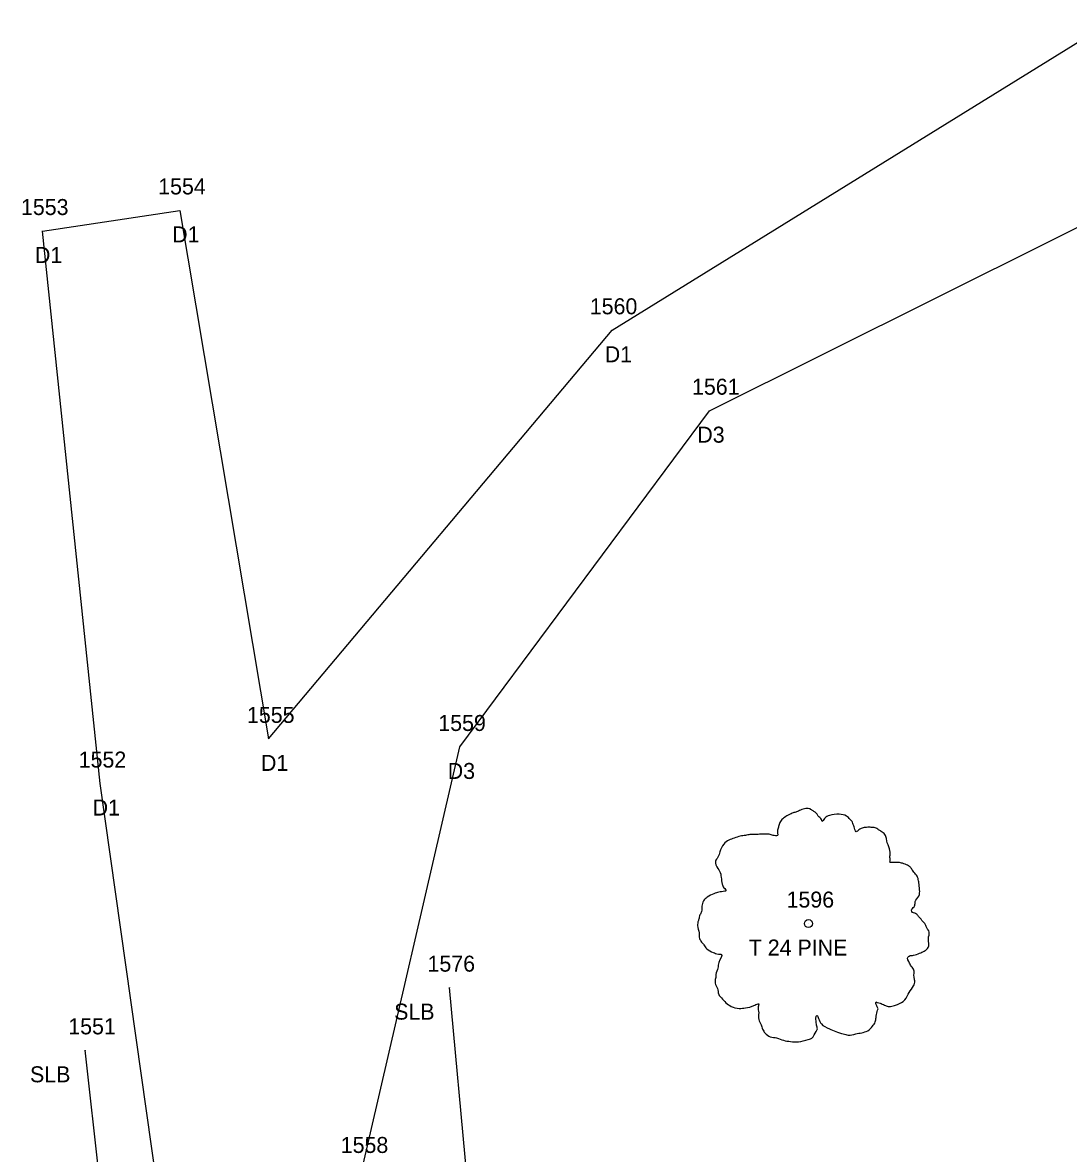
# Model space of a CAD drawing. Extents: x 1965304 to 1970247, y 1117014 to 1118201.
# Drawn here: x 1966566.7 to 1966632.2, y 1117457.6 to 1117528.3 of the extents above; entities that cross this region are included whole.
import ezdxf

# ---------------------------------------------------------------- set-up
doc = ezdxf.new("R2010")
doc.units = 0
for name, color, linetype in [('RD_EX_Driveway', 7, 'Continuous'), ('RD_EX_Driveway_txCode', 7, 'Continuous'), ('RD_EX_VEG', 7, 'Continuous'), ('RD_EX_VEG_txCode', 7, 'Continuous'), ('RD_SMD_Locator', 7, 'Continuous')]:
    doc.layers.add(name, color=color, linetype=linetype)

msp = doc.modelspace()

# ---------------------------------------------------------------- linework, layer by layer
at = {"layer": 'RD_EX_Driveway'}
for points in [[(1966578.028, 1117435.239), (1966571.581, 1117480.753), (1966567.97, 1117515.311), (1966576.556, 1117516.6), (1966582.112, 1117483.547), (1966603.624, 1117509.102), (1966634.749, 1117528.345), (1966662.085, 1117526.43), (1966689.524, 1117514.663), (1966711.523, 1117497.722), (1966730.008, 1117478.512), (1966744.031, 1117462.693), (1966734.107, 1117458.19)], [(1966589.3, 1117436.331), (1966587.977, 1117456.65), (1966594.083, 1117483.042), (1966609.697, 1117504.074), (1966638.325, 1117518.314), (1966661.317, 1117517.134), (1966685.434, 1117507.038), (1966705.558, 1117491.043), (1966722.871, 1117472.119), (1966734.107, 1117458.19)]]:
    msp.add_lwpolyline(points, dxfattribs=at)
at = {"layer": 'RD_EX_VEG'}
for p, q in [((1966597.045, 1117429.245), (1966593.432, 1117467.989)), ((1966574.062, 1117433.028), (1966570.646, 1117464.069))]:
    msp.add_line(p, q, dxfattribs=at)
for centre, radius in [((1966615.898, 1117471.997), 0.25), ((1966615.898, 1117471.997), 0.25), ((1966615.886, 1117471.978), 0.0001), ((1966615.886, 1117471.978), 0.0001)]:
    msp.add_circle(centre, radius, dxfattribs=at)
for points in [[(1966616.03, 1117479.164), (1966615.73, 1117479.189), (1966615.405, 1117479.089), (1966615.156, 1117478.989), (1966614.931, 1117478.914), (1966614.706, 1117478.814), (1966614.406, 1117478.639), (1966614.181, 1117478.439), (1966614.056, 1117478.189), (1966614.006, 1117477.965), (1966613.956, 1117477.69), (1966613.956, 1117477.515), (1966613.831, 1117477.49), (1966613.681, 1117477.515), (1966613.431, 1117477.59), (1966613.181, 1117477.59), (1966612.931, 1117477.59), (1966612.582, 1117477.565), (1966612.232, 1117477.565), (1966611.957, 1117477.515), (1966611.632, 1117477.465), (1966611.257, 1117477.34), (1966610.907, 1117477.215), (1966610.608, 1117476.965), (1966610.358, 1117476.49), (1966610.233, 1117476.14), (1966610.083, 1117475.89), (1966610.233, 1117475.441), (1966610.408, 1117475.091), (1966610.433, 1117474.891), (1966610.508, 1117474.466), (1966610.608, 1117474.241), (1966610.732, 1117474.041), (1966610.658, 1117474.016), (1966610.283, 1117473.966), (1966609.983, 1117473.866), (1966609.558, 1117473.641), (1966609.333, 1117473.417), (1966609.233, 1117473.092), (1966609.208, 1117472.742), (1966609.108, 1117472.542), (1966609.033, 1117472.267), (1966609.008, 1117472.192), (1966608.958, 1117471.867), (1966609.058, 1117471.417), (1966609.083, 1117471.068), (1966609.208, 1117470.843), (1966609.358, 1117470.668), (1966609.533, 1117470.418), (1966609.933, 1117470.193), (1966610.258, 1117470.093), (1966610.458, 1117470.068), (1966610.283, 1117469.568), (1966610.233, 1117469.218), (1966610.108, 1117468.819), (1966610.108, 1117468.744), (1966610.058, 1117468.269), (1966610.208, 1117467.944), (1966610.283, 1117467.569), (1966610.458, 1117467.344), (1966610.732, 1117467.044), (1966611.057, 1117466.819), (1966611.557, 1117466.694), (1966611.957, 1117466.719), (1966612.532, 1117466.894), (1966612.782, 1117466.969), (1966612.757, 1117466.794), (1966612.782, 1117466.42), (1966612.782, 1117465.995), (1966612.931, 1117465.67), (1966613.031, 1117465.395), (1966613.181, 1117465.145), (1966613.506, 1117464.92), (1966613.906, 1117464.845), (1966614.331, 1117464.695), (1966614.781, 1117464.62), (1966615.28, 1117464.595), (1966615.88, 1117464.745), (1966616.155, 1117464.87), (1966616.255, 1117465.045), (1966616.455, 1117465.42), (1966616.405, 1117465.645), (1966616.43, 1117466.245), (1966616.53, 1117466.07), (1966616.705, 1117465.72), (1966617.205, 1117465.42), (1966617.604, 1117465.245), (1966618.079, 1117465.095), (1966618.379, 1117465.02), (1966618.854, 1117465.095), (1966619.229, 1117465.17), (1966619.604, 1117465.295), (1966619.903, 1117465.57), (1966620.078, 1117465.845), (1966620.128, 1117466.12), (1966620.203, 1117466.495), (1966620.253, 1117466.669)], [(1966616.03, 1117479.164), (1966615.73, 1117479.189), (1966615.405, 1117479.089), (1966615.156, 1117478.989), (1966614.931, 1117478.914), (1966614.706, 1117478.814), (1966614.406, 1117478.639), (1966614.181, 1117478.439), (1966614.056, 1117478.189), (1966614.006, 1117477.965), (1966613.956, 1117477.69), (1966613.956, 1117477.515), (1966613.831, 1117477.49), (1966613.681, 1117477.515), (1966613.431, 1117477.59), (1966613.181, 1117477.59), (1966612.931, 1117477.59), (1966612.582, 1117477.565), (1966612.232, 1117477.565), (1966611.957, 1117477.515), (1966611.632, 1117477.465), (1966611.257, 1117477.34), (1966610.907, 1117477.215), (1966610.608, 1117476.965), (1966610.358, 1117476.49), (1966610.233, 1117476.14), (1966610.083, 1117475.89), (1966610.233, 1117475.441), (1966610.408, 1117475.091), (1966610.433, 1117474.891), (1966610.508, 1117474.466), (1966610.608, 1117474.241), (1966610.732, 1117474.041), (1966610.658, 1117474.016), (1966610.283, 1117473.966), (1966609.983, 1117473.866), (1966609.558, 1117473.641), (1966609.333, 1117473.417), (1966609.233, 1117473.092), (1966609.208, 1117472.742), (1966609.108, 1117472.542), (1966609.033, 1117472.267), (1966609.008, 1117472.192), (1966608.958, 1117471.867), (1966609.058, 1117471.417), (1966609.083, 1117471.068), (1966609.208, 1117470.843), (1966609.358, 1117470.668), (1966609.533, 1117470.418), (1966609.933, 1117470.193), (1966610.258, 1117470.093), (1966610.458, 1117470.068), (1966610.283, 1117469.568), (1966610.233, 1117469.218), (1966610.108, 1117468.819), (1966610.108, 1117468.744), (1966610.058, 1117468.269), (1966610.208, 1117467.944), (1966610.283, 1117467.569), (1966610.458, 1117467.344), (1966610.732, 1117467.044), (1966611.057, 1117466.819), (1966611.557, 1117466.694), (1966611.957, 1117466.719), (1966612.532, 1117466.894), (1966612.782, 1117466.969), (1966612.757, 1117466.794), (1966612.782, 1117466.42), (1966612.782, 1117465.995), (1966612.931, 1117465.67), (1966613.031, 1117465.395), (1966613.181, 1117465.145), (1966613.506, 1117464.92), (1966613.906, 1117464.845), (1966614.331, 1117464.695), (1966614.781, 1117464.62), (1966615.28, 1117464.595), (1966615.88, 1117464.745), (1966616.155, 1117464.87), (1966616.255, 1117465.045), (1966616.455, 1117465.42), (1966616.405, 1117465.645), (1966616.43, 1117466.245), (1966616.53, 1117466.07), (1966616.705, 1117465.72), (1966617.205, 1117465.42), (1966617.604, 1117465.245), (1966618.079, 1117465.095), (1966618.379, 1117465.02), (1966618.854, 1117465.095), (1966619.229, 1117465.17), (1966619.604, 1117465.295), (1966619.903, 1117465.57), (1966620.078, 1117465.845), (1966620.128, 1117466.12), (1966620.203, 1117466.495), (1966620.253, 1117466.669)], [(1966620.253, 1117466.669), (1966620.178, 1117466.844), (1966620.128, 1117467.094), (1966620.203, 1117467.069), (1966620.378, 1117467.019), (1966620.653, 1117466.894), (1966620.878, 1117466.819), (1966621.203, 1117466.844), (1966621.478, 1117466.944), (1966621.928, 1117467.219), (1966622.202, 1117467.694), (1966622.477, 1117468.094), (1966622.552, 1117468.419), (1966622.502, 1117468.644), (1966622.477, 1117469.143), (1966622.277, 1117469.393), (1966622.227, 1117469.518), (1966622.127, 1117469.918), (1966622.202, 1117469.968), (1966622.477, 1117470.018), (1966622.852, 1117470.143), (1966623.127, 1117470.268), (1966623.352, 1117470.443), (1966623.427, 1117470.668), (1966623.402, 1117471.068), (1966623.452, 1117471.467), (1966623.377, 1117471.617), (1966623.277, 1117471.767), (1966623.202, 1117471.967), (1966623.052, 1117472.117), (1966622.952, 1117472.267), (1966622.852, 1117472.367), (1966622.727, 1117472.517), (1966622.552, 1117472.642), (1966622.402, 1117472.692), (1966622.352, 1117472.842), (1966622.502, 1117473.042), (1966622.552, 1117473.142), (1966622.577, 1117473.367), (1966622.802, 1117473.716), (1966622.852, 1117474.116), (1966622.802, 1117474.541), (1966622.752, 1117474.816), (1966622.602, 1117475.091), (1966622.402, 1117475.341), (1966622.277, 1117475.516), (1966622.102, 1117475.641), (1966621.778, 1117475.766), (1966621.528, 1117475.815), (1966621.178, 1117475.815), (1966620.978, 1117475.865), (1966621.003, 1117475.915), (1966621.003, 1117476.065), (1966621.003, 1117476.34), (1966620.928, 1117476.79), (1966620.778, 1117477.29), (1966620.778, 1117477.315), (1966620.678, 1117477.565), (1966620.453, 1117477.765), (1966620.278, 1117477.865), (1966620.078, 1117477.99), (1966619.828, 1117478.015), (1966619.529, 1117478.015), (1966619.254, 1117477.965), (1966619.054, 1117477.865), (1966618.879, 1117477.74), (1966618.804, 1117477.89), (1966618.704, 1117478.189), (1966618.654, 1117478.339), (1966618.504, 1117478.514), (1966618.279, 1117478.714), (1966617.829, 1117478.839), (1966617.205, 1117478.764), (1966616.905, 1117478.564), (1966616.755, 1117478.389), (1966616.705, 1117478.514), (1966616.505, 1117478.714), (1966616.405, 1117478.889), (1966616.23, 1117479.014), (1966616.08, 1117479.114), (1966615.98, 1117479.164)], [(1966620.253, 1117466.669), (1966620.178, 1117466.844), (1966620.128, 1117467.094), (1966620.203, 1117467.069), (1966620.378, 1117467.019), (1966620.653, 1117466.894), (1966620.878, 1117466.819), (1966621.203, 1117466.844), (1966621.478, 1117466.944), (1966621.928, 1117467.219), (1966622.202, 1117467.694), (1966622.477, 1117468.094), (1966622.552, 1117468.419), (1966622.502, 1117468.644), (1966622.477, 1117469.143), (1966622.277, 1117469.393), (1966622.227, 1117469.518), (1966622.127, 1117469.918), (1966622.202, 1117469.968), (1966622.477, 1117470.018), (1966622.852, 1117470.143), (1966623.127, 1117470.268), (1966623.352, 1117470.443), (1966623.427, 1117470.668), (1966623.402, 1117471.068), (1966623.452, 1117471.467), (1966623.377, 1117471.617), (1966623.277, 1117471.767), (1966623.202, 1117471.967), (1966623.052, 1117472.117), (1966622.952, 1117472.267), (1966622.852, 1117472.367), (1966622.727, 1117472.517), (1966622.552, 1117472.642), (1966622.402, 1117472.692), (1966622.352, 1117472.842), (1966622.502, 1117473.042), (1966622.552, 1117473.142), (1966622.577, 1117473.367), (1966622.802, 1117473.716), (1966622.852, 1117474.116), (1966622.802, 1117474.541), (1966622.752, 1117474.816), (1966622.602, 1117475.091), (1966622.402, 1117475.341), (1966622.277, 1117475.516), (1966622.102, 1117475.641), (1966621.778, 1117475.766), (1966621.528, 1117475.815), (1966621.178, 1117475.815), (1966620.978, 1117475.865), (1966621.003, 1117475.915), (1966621.003, 1117476.065), (1966621.003, 1117476.34), (1966620.928, 1117476.79), (1966620.778, 1117477.29), (1966620.778, 1117477.315), (1966620.678, 1117477.565), (1966620.453, 1117477.765), (1966620.278, 1117477.865), (1966620.078, 1117477.99), (1966619.828, 1117478.015), (1966619.529, 1117478.015), (1966619.254, 1117477.965), (1966619.054, 1117477.865), (1966618.879, 1117477.74), (1966618.804, 1117477.89), (1966618.704, 1117478.189), (1966618.654, 1117478.339), (1966618.504, 1117478.514), (1966618.279, 1117478.714), (1966617.829, 1117478.839), (1966617.205, 1117478.764), (1966616.905, 1117478.564), (1966616.755, 1117478.389), (1966616.705, 1117478.514), (1966616.505, 1117478.714), (1966616.405, 1117478.889), (1966616.23, 1117479.014), (1966616.08, 1117479.114), (1966615.98, 1117479.164)]]:
    msp.add_spline(points, degree=3, dxfattribs=at)
at = {"layer": 'RD_SMD_Locator'}
for centre in [(1966576.556, 1117516.6), (1966576.556, 1117516.6), (1966567.97, 1117515.311), (1966567.97, 1117515.311), (1966603.624, 1117509.102), (1966603.624, 1117509.102), (1966609.697, 1117504.074), (1966609.697, 1117504.074), (1966582.112, 1117483.547), (1966582.112, 1117483.547), (1966594.083, 1117483.042), (1966594.083, 1117483.042), (1966571.581, 1117480.753), (1966571.581, 1117480.753), (1966593.432, 1117467.989), (1966593.432, 1117467.989), (1966570.646, 1117464.069), (1966570.646, 1117464.069)]:
    msp.add_circle(centre, 0.001, dxfattribs=at)

# ---------------------------------------------------------------- texts
at = {"layer": 'RD_EX_Driveway_txCode'}
for s, p in [('1554', (1966575.209, 1117517.6)), ('1554', (1966575.209, 1117517.6)), ('1553', (1966566.623, 1117516.311)), ('1553', (1966566.623, 1117516.311)), ('D1', (1966576.083, 1117514.6)), ('D1', (1966576.083, 1117514.6)), ('D1', (1966567.497, 1117513.311)), ('D1', (1966567.497, 1117513.311)), ('1560', (1966602.215, 1117510.102)), ('1560', (1966602.215, 1117510.102)), ('D1', (1966603.152, 1117507.102)), ('D1', (1966603.152, 1117507.102)), ('1561', (1966608.611, 1117505.074)), ('1561', (1966608.611, 1117505.074)), ('D3', (1966608.941, 1117502.074)), ('D3', (1966608.941, 1117502.074)), ('1555', (1966580.765, 1117484.547)), ('1555', (1966580.765, 1117484.547)), ('1559', (1966592.736, 1117484.042)), ('1559', (1966592.736, 1117484.042)), ('1552', (1966570.235, 1117481.753)), ('1552', (1966570.235, 1117481.753)), ('D1', (1966581.639, 1117481.547)), ('D1', (1966581.639, 1117481.547)), ('D3', (1966593.327, 1117481.042)), ('D3', (1966593.327, 1117481.042)), ('D1', (1966571.109, 1117478.753)), ('D1', (1966571.109, 1117478.753)), ('1558', (1966586.631, 1117457.65)), ('1558', (1966586.631, 1117457.65))]:
    msp.add_text(s, height=1, dxfattribs=at).set_placement(p)
at = {"layer": 'RD_EX_VEG_txCode'}
for s, p in [('1596', (1966614.528, 1117472.997)), ('1596', (1966614.528, 1117472.997)), ('T 24 PINE', (1966612.162, 1117469.997)), ('T 24 PINE', (1966612.162, 1117469.997)), ('1576', (1966592.062, 1117468.989)), ('1576', (1966592.062, 1117468.989)), ('SLB', (1966589.975, 1117465.989)), ('SLB', (1966589.975, 1117465.989)), ('1551', (1966569.583, 1117465.069)), ('1551', (1966569.583, 1117465.069)), ('SLB', (1966567.189, 1117462.069)), ('SLB', (1966567.189, 1117462.069))]:
    msp.add_text(s, height=1, dxfattribs=at).set_placement(p)

doc.saveas('drawing.dxf')
